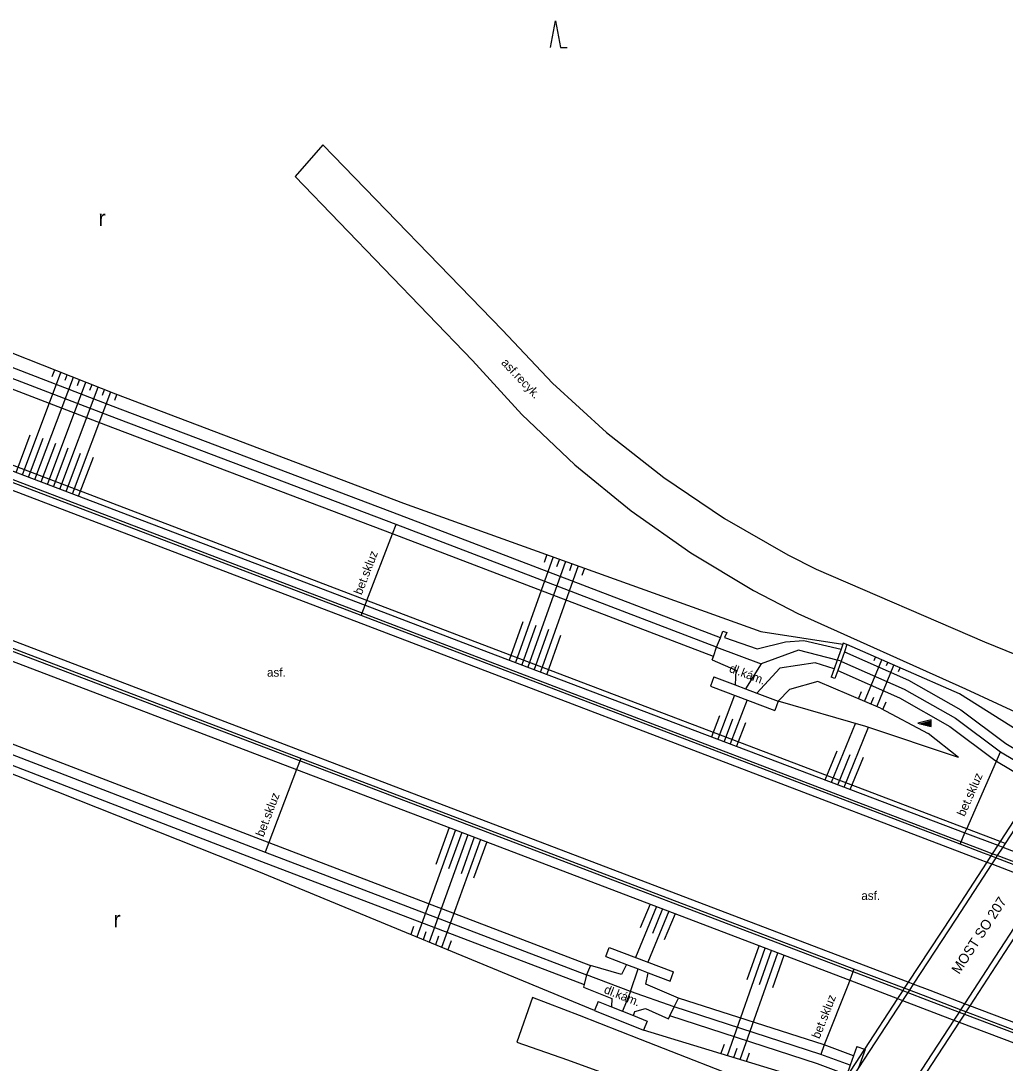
# Model space of a CAD drawing. Extents: x -541281 to -539153, y -1183881 to -1182141.
# Drawn here: x -539332.2 to -539258.6, y -1182483.7 to -1182405.7 of the extents above; entities that cross this region are included whole.
import ezdxf

# ---------------------------------------------------------------- set-up
doc = ezdxf.new("R2010")
doc.units = 0
for name, color, linetype in [('Vrstva 10', 7, 'Continuous'), ('Vrstva 11', 7, 'Continuous'), ('Vrstva 14', 7, 'Continuous'), ('Vrstva 15', 7, 'Continuous'), ('Vrstva 28', 7, 'Continuous'), ('Vrstva 36', 7, 'Continuous'), ('Vrstva 40', 7, 'Continuous'), ('Vrstva 41', 7, 'Continuous'), ('Vrstva 7', 7, 'Continuous'), ('Vrstva 9', 7, 'Continuous')]:
    doc.layers.add(name, color=color, linetype=linetype)

msp = doc.modelspace()

# ---------------------------------------------------------------- linework, layer by layer
at = {"layer": 'Vrstva 10'}
for p, q in [((-539335.258, -1182439.945), (-539297.88, -1182454.193)), ((-539301.621, -1182464.028), (-539339.016, -1182449.749)), ((-539297.88, -1182454.193), (-539260.528, -1182468.452)), ((-539265.877, -1182477.638), (-539301.621, -1182464.028)), ((-539260.528, -1182468.452), (-539260.006, -1182468.652)), ((-539260.006, -1182468.652), (-539259.63, -1182468.795)), ((-539259.63, -1182468.795), (-539255.807, -1182470.254)), ((-539265.501, -1182477.781), (-539265.877, -1182477.638)), ((-539264.234, -1182478.264), (-539265.501, -1182477.781)), ((-539261.67, -1182479.244), (-539264.234, -1182478.264)), ((-539261.274, -1182479.395), (-539261.67, -1182479.244)), ((-539226.842, -1182492.543), (-539261.274, -1182479.395))]:
    msp.add_line(p, q, dxfattribs=at)
for points in [[(-539254.464, -1182460.158), (-539254.787, -1182460.649), (-539255.436, -1182461.648), (-539255.847, -1182462.277), (-539256.257, -1182462.906), (-539259.001, -1182467.111), (-539259.19, -1182467.401), (-539259.599, -1182468.028), (-539259.711, -1182468.199), (-539260.006, -1182468.652), (-539262.655, -1182472.712)], [(-539254.135, -1182460.373), (-539254.416, -1182460.803), (-539255.607, -1182462.627), (-539255.919, -1182463.106), (-539258.625, -1182467.254), (-539258.814, -1182467.544), (-539259.223, -1182468.171), (-539259.335, -1182468.342), (-539259.63, -1182468.795), (-539262.326, -1182472.927)], [(-539250.806, -1182462.595), (-539251.77, -1182464.071), (-539254.797, -1182468.708), (-539254.985, -1182468.995), (-539255.397, -1182469.626), (-539255.509, -1182469.797), (-539255.807, -1182470.254), (-539259.025, -1182475.182)], [(-539250.459, -1182462.821), (-539250.684, -1182463.166), (-539252.201, -1182465.489), (-539254.401, -1182468.859), (-539254.589, -1182469.146), (-539255.001, -1182469.777), (-539255.113, -1182469.948), (-539255.411, -1182470.405), (-539258.678, -1182475.408)], [(-539262.655, -1182472.712), (-539265.877, -1182477.638), (-539266.175, -1182478.094), (-539266.287, -1182478.266), (-539266.677, -1182478.861), (-539269.157, -1182482.653), (-539270.546, -1182484.777), (-539270.844, -1182485.232)], [(-539262.326, -1182472.927), (-539265.501, -1182477.781), (-539265.799, -1182478.237), (-539265.912, -1182478.409), (-539266.301, -1182479.004), (-539269.601, -1182484.049), (-539270.516, -1182485.448)], [(-539259.025, -1182475.182), (-539261.67, -1182479.244), (-539261.967, -1182479.7), (-539262.078, -1182479.87), (-539262.466, -1182480.466), (-539265.282, -1182484.791), (-539265.7, -1182485.433), (-539265.847, -1182485.659), (-539266.82, -1182487.153), (-539267.166, -1182487.685)], [(-539258.678, -1182475.408), (-539261.274, -1182479.395), (-539261.571, -1182479.851), (-539261.682, -1182480.022), (-539262.07, -1182480.617), (-539264.886, -1182484.943), (-539265.305, -1182485.586), (-539265.723, -1182486.228), (-539266.434, -1182487.292), (-539266.82, -1182487.913)]]:
    msp.add_lwpolyline(points, dxfattribs=at)
at = {"layer": 'Vrstva 11'}
for p, q in [((-539309.655, -1182415.01), (-539311.718, -1182417.394)), ((-539309.655, -1182415.01), (-539296.234, -1182428.868)), ((-539311.718, -1182417.394), (-539298.458, -1182431.143)), ((-539325.348, -1182434.576), (-539352.341, -1182424.213)), ((-539325.882, -1182435.978), (-539352.875, -1182425.615)), ((-539303.908, -1182442.711), (-539325.348, -1182434.576)), ((-539304.442, -1182444.113), (-539325.882, -1182435.978)), ((-539279.927, -1182451.887), (-539303.908, -1182442.711)), ((-539280.447, -1182453.293), (-539304.442, -1182444.113)), ((-539272.761, -1182446.76), (-539260.189, -1182452.183)), ((-539274.14, -1182450.056), (-539261.59, -1182455.706)), ((-539279.742, -1182451.388), (-539279.458, -1182451.484)), ((-539279.458, -1182451.484), (-539279.622, -1182451.871)), ((-539279.622, -1182451.871), (-539277.184, -1182452.707)), ((-539277.184, -1182452.707), (-539275.049, -1182452.192)), ((-539275.049, -1182452.192), (-539273.689, -1182452.078)), ((-539273.689, -1182452.078), (-539270.902, -1182452.725)), ((-539270.47, -1182452.395), (-539270.753, -1182452.295)), ((-539280.537, -1182453.537), (-539278.77, -1182454.293)), ((-539272.845, -1182453.753), (-539275.479, -1182454.156)), ((-539271.418, -1182454.208), (-539272.845, -1182453.753)), ((-539280.417, -1182454.81), (-539280.677, -1182455.503)), ((-539278.77, -1182454.293), (-539278.822, -1182455.409)), ((-539275.479, -1182454.156), (-539277.211, -1182456.014)), ((-539271.361, -1182454.925), (-539271.644, -1182454.825)), ((-539280.677, -1182455.503), (-539275.856, -1182457.313)), ((-539261.59, -1182455.706), (-539253.894, -1182459.287)), ((-539275.596, -1182456.62), (-539275.856, -1182457.313)), ((-539338.441, -1182457.667), (-539313.706, -1182467.201)), ((-539338.977, -1182459.069), (-539314.244, -1182468.601)), ((-539313.706, -1182467.201), (-539289.649, -1182476.377)), ((-539259.711, -1182468.199), (-539260.253, -1182467.993)), ((-539259.223, -1182468.171), (-539259.599, -1182468.028)), ((-539314.244, -1182468.601), (-539290.114, -1182477.81)), ((-539259.335, -1182468.342), (-539259.711, -1182468.199)), ((-539255.509, -1182469.797), (-539259.335, -1182468.342)), ((-539255.397, -1182469.626), (-539259.223, -1182468.171)), ((-539288.5, -1182475.724), (-539288.236, -1182475.033)), ((-539288.236, -1182475.033), (-539283.433, -1182476.871)), ((-539287.32, -1182477.07), (-539289.649, -1182476.377)), ((-539286.945, -1182476.319), (-539287.32, -1182477.07)), ((-539285.514, -1182477.796), (-539285.342, -1182476.932)), ((-539283.697, -1182477.562), (-539283.433, -1182476.871)), ((-539290.178, -1182478.007), (-539288.057, -1182478.846)), ((-539283.058, -1182478.826), (-539285.514, -1182477.796)), ((-539266.287, -1182478.266), (-539265.912, -1182478.409)), ((-539265.799, -1182478.237), (-539266.175, -1182478.094)), ((-539264.426, -1182478.761), (-539265.799, -1182478.237)), ((-539293.987, -1182478.771), (-539295.142, -1182482.115)), ((-539290.459, -1182480.126), (-539293.987, -1182478.771)), ((-539288.057, -1182478.846), (-539288.084, -1182479.471)), ((-539265.912, -1182478.409), (-539264.497, -1182478.948)), ((-539264.497, -1182478.948), (-539262.078, -1182479.87)), ((-539261.967, -1182479.7), (-539264.426, -1182478.761)), ((-539289.079, -1182479.074), (-539289.353, -1182479.761)), ((-539289.353, -1182479.761), (-539285.681, -1182481.226)), ((-539286.434, -1182480.129), (-539286.316, -1182479.819)), ((-539286.316, -1182479.819), (-539285.528, -1182479.598)), ((-539285.528, -1182479.598), (-539283.821, -1182480.383)), ((-539261.571, -1182479.851), (-539261.967, -1182479.7)), ((-539285.898, -1182481.932), (-539290.459, -1182480.126)), ((-539285.407, -1182480.539), (-539285.681, -1182481.226)), ((-539262.078, -1182479.87), (-539261.682, -1182480.022)), ((-539227.034, -1182493.036), (-539261.571, -1182479.851)), ((-539295.142, -1182482.115), (-539291.366, -1182483.454)), ((-539272.183, -1182487.269), (-539285.898, -1182481.932)), ((-539269.727, -1182482.452), (-539269.157, -1182482.653)), ((-539291.366, -1182483.454), (-539286.504, -1182485.213))]:
    msp.add_line(p, q, dxfattribs=at)
for points in [[(-539296.234, -1182428.868), (-539292.481, -1182432.839), (-539288.447, -1182436.525), (-539284.155, -1182439.907), (-539279.627, -1182442.965), (-539274.888, -1182445.684), (-539272.761, -1182446.76)], [(-539298.458, -1182431.143), (-539294.782, -1182435.182), (-539290.82, -1182438.941), (-539286.594, -1182442.4), (-539282.127, -1182445.541), (-539277.441, -1182448.346), (-539274.14, -1182450.056)], [(-539297.727, -1182453.687), (-539306.804, -1182450.222), (-539335.056, -1182439.436)], [(-539301.798, -1182464.518), (-539311.302, -1182460.897), (-539339.187, -1182450.275)], [(-539280.537, -1182453.537), (-539280.447, -1182453.293), (-539280.223, -1182452.576), (-539279.927, -1182451.887), (-539279.742, -1182451.388)], [(-539270.753, -1182452.295), (-539270.772, -1182452.349), (-539270.902, -1182452.725), (-539271.193, -1182453.563), (-539271.418, -1182454.208), (-539271.644, -1182454.825)], [(-539270.47, -1182452.395), (-539270.655, -1182452.921), (-539270.907, -1182453.637), (-539271.155, -1182454.34), (-539271.361, -1182454.925)], [(-539260.189, -1182452.183), (-539252.208, -1182455.434), (-539251.566, -1182455.729)], [(-539270.655, -1182452.921), (-539265.858, -1182455.042), (-539261.946, -1182457.267), (-539258.572, -1182459.791), (-539255.436, -1182461.648)], [(-539260.253, -1182467.993), (-539262.01, -1182467.322), (-539297.727, -1182453.687)], [(-539280.417, -1182454.81), (-539278.822, -1182455.409), (-539278.057, -1182455.696), (-539277.211, -1182456.014), (-539275.596, -1182456.62)], [(-539271.155, -1182454.34), (-539266.534, -1182456.384), (-539262.77, -1182458.525), (-539259.406, -1182461.041), (-539259.292, -1182461.109), (-539256.257, -1182462.906)], [(-539266.175, -1182478.094), (-539269.945, -1182476.658), (-539301.798, -1182464.518)], [(-539288.5, -1182475.724), (-539286.945, -1182476.319), (-539286.085, -1182476.648), (-539285.342, -1182476.932), (-539283.697, -1182477.562)], [(-539289.649, -1182476.377), (-539289.932, -1182477.077), (-539290.114, -1182477.81), (-539290.178, -1182478.007)], [(-539283.821, -1182480.383), (-539283.709, -1182480.155), (-539283.381, -1182479.473), (-539283.058, -1182478.826)], [(-539269.97, -1182483.141), (-539272.174, -1182482.324), (-539283.058, -1182478.826)], [(-539289.079, -1182479.074), (-539288.084, -1182479.471), (-539287.262, -1182479.799), (-539286.434, -1182480.129), (-539285.407, -1182480.539)], [(-539270.468, -1182484.555), (-539272.666, -1182483.742), (-539283.709, -1182480.155)], [(-539269.727, -1182482.452), (-539269.97, -1182483.141), (-539270.219, -1182483.848), (-539270.468, -1182484.555), (-539270.546, -1182484.777)], [(-539269.157, -1182482.653), (-539269.114, -1182482.668), (-539269.601, -1182484.049)]]:
    msp.add_lwpolyline(points, dxfattribs=at)
at = {"layer": 'Vrstva 14'}
for p, q in [((-539351.949, -1182423.078), (-539325.164, -1182433.64)), ((-539325.615, -1182435.277), (-539352.608, -1182424.914)), ((-539325.164, -1182433.64), (-539303.639, -1182441.808)), ((-539304.175, -1182443.412), (-539325.615, -1182435.277)), ((-539303.639, -1182441.808), (-539276.914, -1182451.418)), ((-539280.223, -1182452.576), (-539304.175, -1182443.412)), ((-539306.804, -1182450.222), (-539306.505, -1182449.448)), ((-539306.505, -1182449.448), (-539306.369, -1182449.095)), ((-539276.914, -1182451.418), (-539270.772, -1182452.349)), ((-539262.058, -1182456.082), (-539270.47, -1182452.395)), ((-539280.223, -1182452.576), (-539276.882, -1182453.826)), ((-539274.082, -1182452.805), (-539276.882, -1182453.826)), ((-539271.193, -1182453.563), (-539274.082, -1182452.805)), ((-539276.882, -1182453.826), (-539278.057, -1182455.696)), ((-539270.907, -1182453.637), (-539271.193, -1182453.563)), ((-539270.866, -1182453.648), (-539270.907, -1182453.637)), ((-539272.647, -1182455.142), (-539274.768, -1182455.747)), ((-539267.958, -1182457.157), (-539272.647, -1182455.142)), ((-539274.768, -1182455.747), (-539275.596, -1182456.62)), ((-539254.787, -1182460.649), (-539262.058, -1182456.082)), ((-539269.061, -1182458.504), (-539275.596, -1182456.62)), ((-539267.958, -1182457.157), (-539264.389, -1182459.041)), ((-539338.709, -1182458.368), (-539313.975, -1182467.901)), ((-539262.118, -1182460.823), (-539269.061, -1182458.504)), ((-539262.118, -1182460.823), (-539264.389, -1182459.041)), ((-539314.443, -1182469.381), (-539338.778, -1182459.747)), ((-539311.302, -1182460.897), (-539311.619, -1182461.728)), ((-539261.502, -1182466.161), (-539259.292, -1182461.109)), ((-539259.292, -1182461.109), (-539258.989, -1182460.416)), ((-539262.01, -1182467.322), (-539261.638, -1182466.473)), ((-539261.638, -1182466.473), (-539261.502, -1182466.161)), ((-539313.975, -1182467.901), (-539289.932, -1182477.077)), ((-539259.19, -1182467.401), (-539258.814, -1182467.544)), ((-539258.814, -1182467.544), (-539254.985, -1182468.995)), ((-539289.353, -1182479.761), (-539314.443, -1182469.381)), ((-539286.646, -1182478.323), (-539286.085, -1182476.648)), ((-539269.945, -1182476.658), (-539270.256, -1182477.496)), ((-539286.646, -1182478.323), (-539289.932, -1182477.077)), ((-539270.256, -1182477.496), (-539270.356, -1182477.767)), ((-539286.646, -1182478.323), (-539287.262, -1182479.799)), ((-539283.381, -1182479.473), (-539286.646, -1182478.323)), ((-539266.677, -1182478.861), (-539266.301, -1182479.004)), ((-539266.301, -1182479.004), (-539262.466, -1182480.466)), ((-539262.466, -1182480.466), (-539262.07, -1182480.617)), ((-539262.07, -1182480.617), (-539227.308, -1182493.872)), ((-539271.115, -1182485.645), (-539285.681, -1182481.226))]:
    msp.add_line(p, q, dxfattribs=at)
for points in [[(-539354.984, -1182430.997), (-539306.505, -1182449.448), (-539297.285, -1182452.957)], [(-539376.773, -1182436.915), (-539358.275, -1182443.96), (-539311.619, -1182461.728), (-539301.862, -1182465.444)], [(-539306.369, -1182449.095), (-539304.442, -1182444.113), (-539304.175, -1182443.412)], [(-539297.285, -1182452.957), (-539261.638, -1182466.473), (-539259.19, -1182467.401)], [(-539270.866, -1182453.648), (-539266.196, -1182455.713), (-539262.358, -1182457.896), (-539258.989, -1182460.416), (-539255.847, -1182462.277)], [(-539311.619, -1182461.728), (-539313.706, -1182467.201), (-539313.975, -1182467.901)], [(-539301.862, -1182465.444), (-539270.256, -1182477.496), (-539266.677, -1182478.861)], [(-539270.356, -1182477.767), (-539272.174, -1182482.324), (-539272.42, -1182483.033)], [(-539270.219, -1182483.848), (-539272.42, -1182483.033), (-539283.381, -1182479.473)]]:
    msp.add_lwpolyline(points, dxfattribs=at)
at = {"layer": 'Vrstva 15'}
for p, q in [((-539332.128, -1182439.696), (-539329.242, -1182432.032)), ((-539329.893, -1182432.338), (-539329.708, -1182431.848)), ((-539328.93, -1182432.621), (-539328.777, -1182432.215)), ((-539331.193, -1182440.051), (-539328.312, -1182432.399)), ((-539330.259, -1182440.407), (-539327.382, -1182432.766)), ((-539328.007, -1182433.007), (-539327.847, -1182432.582)), ((-539327.078, -1182433.377), (-539326.917, -1182432.949)), ((-539329.324, -1182440.763), (-539326.451, -1182433.133)), ((-539328.389, -1182441.119), (-539325.52, -1182433.5)), ((-539326.149, -1182433.749), (-539325.986, -1182433.316)), ((-539325.213, -1182434.102), (-539325.055, -1182433.682)), ((-539332.596, -1182439.518), (-539331.54, -1182436.714)), ((-539331.661, -1182439.873), (-539330.564, -1182436.959)), ((-539330.726, -1182440.229), (-539329.634, -1182437.33)), ((-539329.792, -1182440.585), (-539328.701, -1182437.687)), ((-539328.857, -1182440.941), (-539327.774, -1182438.065)), ((-539327.922, -1182441.297), (-539326.818, -1182438.365)), ((-539292.443, -1182445.834), (-539295.258, -1182453.726)), ((-539291.502, -1182446.172), (-539294.323, -1182454.08)), ((-539292.914, -1182445.665), (-539293.12, -1182446.242)), ((-539291.973, -1182446.003), (-539292.177, -1182446.576)), ((-539290.561, -1182446.511), (-539293.387, -1182454.435)), ((-539291.032, -1182446.341), (-539291.225, -1182446.882)), ((-539290.091, -1182446.68), (-539290.289, -1182447.235)), ((-539294.706, -1182450.688), (-539295.726, -1182453.548)), ((-539293.74, -1182450.958), (-539294.79, -1182453.903)), ((-539292.791, -1182451.273), (-539293.855, -1182454.257)), ((-539291.882, -1182451.702), (-539292.92, -1182454.612)), ((-539268.428, -1182453.586), (-539268.325, -1182453.335)), ((-539269.142, -1182456.648), (-539267.868, -1182453.536)), ((-539268.222, -1182457.043), (-539266.951, -1182453.937)), ((-539267.503, -1182453.966), (-539267.409, -1182453.737)), ((-539266.6, -1182454.398), (-539266.494, -1182454.138)), ((-539278.873, -1182456.18), (-539280.125, -1182459.463)), ((-539269.6, -1182456.451), (-539269.377, -1182455.906)), ((-539268.682, -1182456.846), (-539268.465, -1182456.317)), ((-539277.937, -1182456.532), (-539279.19, -1182459.818)), ((-539267.77, -1182457.256), (-539267.533, -1182456.677)), ((-539279.99, -1182457.706), (-539280.592, -1182459.286)), ((-539279.018, -1182457.964), (-539279.658, -1182459.641)), ((-539278.051, -1182458.231), (-539278.723, -1182459.995)), ((-539271.615, -1182462.69), (-539269.813, -1182458.287)), ((-539270.679, -1182463.045), (-539268.849, -1182458.575)), ((-539272.082, -1182462.513), (-539271.187, -1182460.327)), ((-539271.147, -1182462.868), (-539270.221, -1182460.606)), ((-539270.212, -1182463.222), (-539269.224, -1182460.809)), ((-539299.743, -1182466.252), (-539302.628, -1182474.269)), ((-539300.209, -1182466.074), (-539301.199, -1182468.825)), ((-539299.274, -1182466.431), (-539300.252, -1182469.148)), ((-539298.808, -1182466.609), (-539301.702, -1182474.652)), ((-539297.873, -1182466.965), (-539300.777, -1182475.035)), ((-539298.341, -1182466.787), (-539299.327, -1182469.526)), ((-539297.406, -1182467.143), (-539298.382, -1182469.855)), ((-539284.719, -1182471.981), (-539286.286, -1182475.779)), ((-539285.186, -1182471.803), (-539285.92, -1182473.582)), ((-539283.784, -1182472.337), (-539285.352, -1182476.137)), ((-539284.252, -1182472.159), (-539285.007, -1182473.99)), ((-539283.318, -1182472.515), (-539284.124, -1182474.469)), ((-539302.874, -1182473.477), (-539303.09, -1182474.078)), ((-539301.955, -1182473.882), (-539302.164, -1182474.461)), ((-539301.003, -1182474.185), (-539301.24, -1182474.843)), ((-539300.07, -1182474.545), (-539300.315, -1182475.226)), ((-539279.409, -1182483.129), (-539276.573, -1182475.087)), ((-539277.928, -1182477.425), (-539277.04, -1182474.909)), ((-539278.45, -1182483.42), (-539275.637, -1182475.444)), ((-539277.002, -1182477.808), (-539276.105, -1182475.265)), ((-539276.018, -1182478.027), (-539275.17, -1182475.622)), ((-539279.888, -1182482.984), (-539279.634, -1182482.264)), ((-539278.93, -1182483.274), (-539278.68, -1182482.565)), ((-539277.972, -1182483.565), (-539277.741, -1182482.909))]:
    msp.add_line(p, q, dxfattribs=at)
at = {"layer": 'Vrstva 28'}
for p, q in [((-539265.03, -1182458.314), (-539264.166, -1182458.1)), ((-539264.884, -1182458.35), (-539264.166, -1182458.172)), ((-539264.739, -1182458.386), (-539264.166, -1182458.244)), ((-539264.593, -1182458.422), (-539264.166, -1182458.316)), ((-539264.448, -1182458.458), (-539264.166, -1182458.389)), ((-539264.302, -1182458.494), (-539264.166, -1182458.461))]:
    msp.add_line(p, q, dxfattribs=at)
msp.add_lwpolyline([(-539264.166, -1182458.028), (-539265.176, -1182458.278), (-539264.166, -1182458.528), (-539264.166, -1182458.028)], dxfattribs=at)
at = {"layer": 'Vrstva 36'}
msp.add_lwpolyline([(-539292.639, -1182407.747), (-539292.264, -1182405.747), (-539291.889, -1182407.747), (-539291.389, -1182407.747)], dxfattribs=at)
at = {"layer": 'Vrstva 7'}
msp.add_line((-539258.625, -1182467.254), (-539259.001, -1182467.111), dxfattribs=at)
for points in [[(-539297.225, -1182452.584), (-539306.369, -1182449.095), (-539354.83, -1182430.602)], [(-539259.001, -1182467.111), (-539261.502, -1182466.161), (-539297.225, -1182452.584)]]:
    msp.add_lwpolyline(points, dxfattribs=at)
at = {"layer": 'Vrstva 9'}
for p, q in [((-539297.656, -1182453.5), (-539334.985, -1182439.249)), ((-539339.258, -1182450.462), (-539301.869, -1182464.705)), ((-539260.182, -1182467.806), (-539297.656, -1182453.5)), ((-539301.869, -1182464.705), (-539266.287, -1182478.266)), ((-539259.599, -1182468.028), (-539260.182, -1182467.806)), ((-539261.682, -1182480.022), (-539227.105, -1182493.223))]:
    msp.add_line(p, q, dxfattribs=at)

# ---------------------------------------------------------------- texts
at = {"layer": 'Vrstva 36'}
for p in [(-539326.444, -1182421.099), (-539325.32, -1182473.535)]:
    msp.add_text('r', height=1.2, dxfattribs=at).set_placement(p)
at = {"layer": 'Vrstva 40'}
for s, rotation, p in [('asf.recyk.', 313.59128, (-539296.36, -1182431.36)), ('bet.skluz', 68.89092, (-539306.761, -1182448.722)), ('dl.kám.', 339.42181, (-539279.324, -1182454.419)), ('bet.skluz', 66.37717, (-539261.669, -1182465.296)), ('bet.skluz', 69.11119, (-539314.098, -1182466.821)), ('dl.kám.', 338.24972, (-539288.689, -1182478.423)), ('bet.skluz', 68.59739, (-539272.519, -1182481.915))]:
    msp.add_text(s, height=0.65, rotation=rotation, dxfattribs=at).set_placement(p)
for p in [(-539313.836, -1182454.792), (-539269.39, -1182471.486)]:
    msp.add_text('asf.', height=0.65, dxfattribs=at).set_placement(p)
at = {"layer": 'Vrstva 41'}
msp.add_text('MOST SO 207', height=0.75, rotation=56.93089, dxfattribs=at).set_placement((-539262.074, -1182477.092))

doc.saveas('drawing.dxf')
